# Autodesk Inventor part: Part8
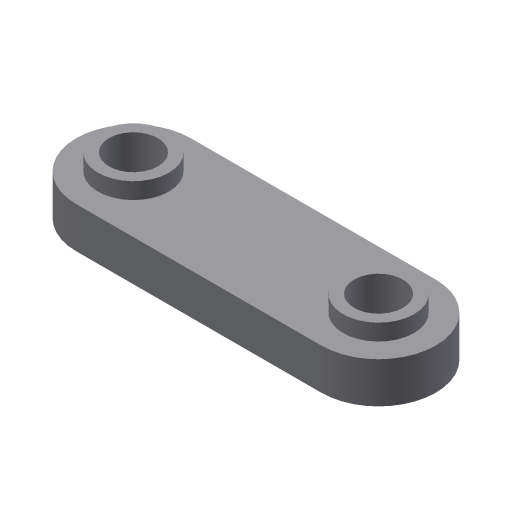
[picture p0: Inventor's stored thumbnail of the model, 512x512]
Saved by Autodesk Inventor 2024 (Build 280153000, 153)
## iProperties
Shininess: 77.0
Length Units: 11269
Angle Units: 11279
Time Units: 11290
Mass Units: 11283
Length Display Precision: 3
Angle Display Precision: 2
Created: 2002-01
Part Number: Part8
Document SubType Name: Modeling
Designer: ***
Density: 1 g/cm^3
Material: Generic
Appearance: Default
Density: 0.0
Volumn: 0.0
Area: 0.0
PropertySet Name: Model Information
Control State: 0
Master: False
Checked Out: False
Author: ***
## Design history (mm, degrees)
sketch "Sketch1"
  geometry: L1 (-33.118, 12.346)-(26.882, 12.361); L2 (-33.111, -15.654)-(26.889, -15.639); C1 r 6 at (-33.114, -1.654); C2 r 6 at (26.886, -1.639); A1 r 14 centre (-33.114, -1.654) between (-33.118, 12.346) and (-33.111, -15.654); A2 r 14 centre (26.886, -1.639) between (26.889, -15.639) and (26.882, 12.361)
  constraints: 4 centre point, 4 end point, 4 point on circle, 4 tangent, 2 coincident, 2 equal radius
  dimensions: "d0" = 60 distance of L1.start L1.end; "d1" = 14 radius of A1; "d2" = 12 diameter of C1
extrude "Extrusion1" new body sketch "Sketch1" distance "d3" = 10; taper "d4" = 0 deg
sketch "Sketch2"
  geometry: C1 r 6 at (26.886, -1.639) reference; C2 r 6 at (-33.114, -1.654) reference; C3 r 8.694 at (-33.114, -1.654); C4 r 8.694 at (26.886, -1.639)
  constraints: 2 centre point, 2 coincident, 1 equal radius
extrude "Extrusion2" join sketch "Sketch2" distance "d5" = 4; taper "d6" = 0 deg
body "Solid1"
